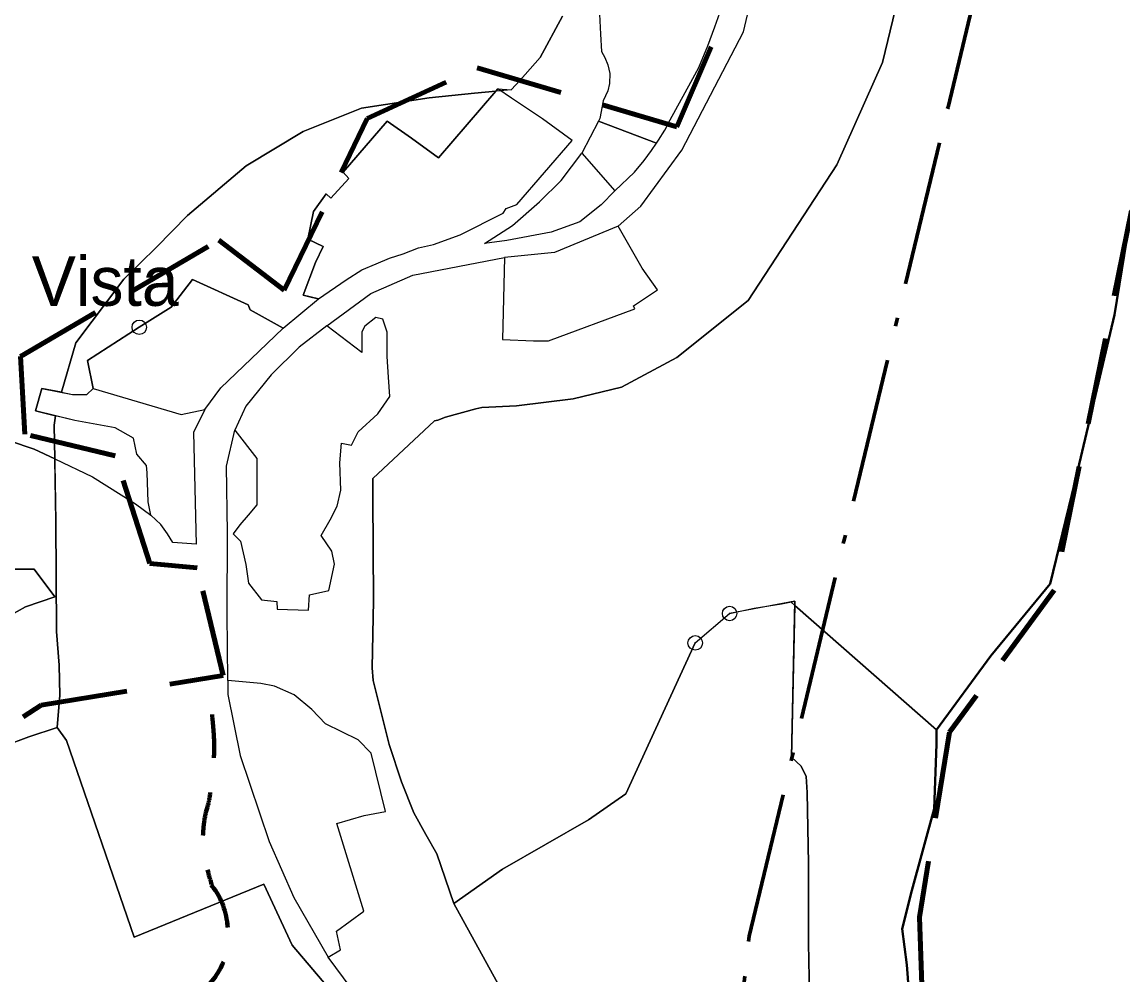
# Model space of a CAD drawing. Extents: x 645880 to 658994, y 884400 to 894744.
# Drawn here: x 657629.6 to 658008.9, y 892199.5 to 892527.8 of the extents above; entities that cross this region are included whole.
import ezdxf
from ezdxf.enums import TextEntityAlignment as Align

# ---------------------------------------------------------------- set-up
doc = ezdxf.new("R2010")
doc.units = 0
doc.header["$LTSCALE"] = 10
doc.header["$PDMODE"] = 32
doc.header["$PDSIZE"] = 5
for name, pattern in [('DOT_DASHED', [7.7, 5, -1.2, 0.3, -1.2]), ('MEDIUM_DASHED', [4.5, 3, -1.5]), ('SHORT_DASHED', [2.7, 1.5, -1.2])]:
    doc.linetypes.add(name, pattern=pattern)
for name, color, linetype, lineweight in [('1', 7, 'Continuous', 25), ('15', 7, 'MEDIUM_DASHED', 100), ('16', 7, 'Continuous', 25), ('17', 7, 'Continuous', 25), ('18', 7, 'Continuous', 25), ('26', 7, 'Continuous', 25), ('41', 7, 'Continuous', 40), ('43', 7, 'Continuous', 25), ('45', 7, 'Continuous', 25), ('54', 7, 'Continuous', 25), ('55', 7, 'Continuous', 25), ('59', 7, 'Continuous', 40), ('8', 7, 'Continuous', 25), ('9', 7, 'Continuous', 25)]:
    doc.layers.add(name, color=color, linetype=linetype, lineweight=lineweight)
doc.layers.add('60', color=7, linetype='Continuous')

msp = doc.modelspace()

# ---------------------------------------------------------------- linework, layer by layer
at = {"layer": '1'}
for points in [[(657833.89, 892469.55), (657829.08, 892464.74), (657821.75, 892458.94), (657811.88, 892455.38), (657796.62, 892452.52), (657788.89, 892451.51), (657798.55, 892457.62), (657807.91, 892465.76), (657815.34, 892473.19), (657822.46, 892482.55)], [(657719.57, 892422.26), (657708.26, 892428.56), (657707.51, 892430.3), (657688.4, 892439), (657680.95, 892429.56), (657670.02, 892422.6), (657652.15, 892411.17), (657654.13, 892401.49), (657684.42, 892392.54), (657692.62, 892394.28), (657698.08, 892401.73), (657708.51, 892411.67)]]:
    msp.add_lwpolyline(points, close=True, dxfattribs=at)
at = {"layer": '15'}
for points in [[(658336.29, 893306.44), (658326.56, 893216.03), (658269.02, 893100.07), (658258.05, 893017.47), (658246.92, 892936.53), (658240.25, 892915.99), (658214.74, 892887.33), (658197.25, 892862.68), (658171.38, 892793.94), (658146.27, 892665.82), (658107.77, 892604.19), (658053.07, 892513.78), (658011.87, 892462.81), (657985.13, 892331.98), (657949.09, 892283.08), (657938.8, 892219.4), (657941.76, 892133.42), (658005.57, 891968.55), (658020.45, 891905.51)], [(657659.98, 891872.19), (657653.31, 891953.19), (657553.31, 891930.32), (657555.21, 891971.29), (657519.02, 892066.59), (657500.92, 892060.88), (657427.26, 892200.13), (657465.85, 892203.1), (657554.9, 892238.74), (657636.17, 892292.45), (657698.87, 892302.6), (657689.96, 892339.72), (657673.64, 892341.21), (657661.76, 892378.34), (657630.59, 892385.76), (657629.11, 892412.49), (657697.38, 892452.59), (657719.98, 892435.41), (657748.55, 892494.5), (657786.44, 892511.99), (657855.22, 892491.64), (657891.81, 892577.33)]]:
    msp.add_lwpolyline(points, dxfattribs=at)
at = {"layer": '16'}
for points in [[(657641.76, 892284.78), (657642.7, 892295.91), (657642.46, 892306.25), (657641.51, 892317.74), (657641.27, 892355.86), (657640.89, 892377.28), (657633.78, 892380.66), (657617.03, 892386.27), (657609.56, 892389.45), (657609.56, 892393.74), (657606.1, 892404.12), (657603.75, 892406.61), (657599.96, 892406.62)], [(657554.13, 892311.79), (657554.13, 892319.84), (657559.4, 892328.64), (657562.22, 892334.26), (657575.23, 892338.19), (657580.1, 892337.81), (657587.04, 892336.67), (657595.08, 892334.91), (657599.56, 892335.75), (657608.31, 892339.25), (657633.81, 892339.25), (657640.93, 892329.75), (657630.81, 892326.25), (657625.11, 892323.1), (657622.12, 892319.05), (657625.15, 892310.12), (657620.91, 892296.57), (657619.41, 892287.86), (657618.04, 892276.14)], [(657618.04, 892276.14), (657623.33, 892278.32), (657631.97, 892281.51), (657641.76, 892284.78)]]:
    msp.add_lwpolyline(points, dxfattribs=at)
at = {"layer": '17'}
for points in [[(657808.16, 892515.52), (657815.77, 892529.8)], [(657792.8, 892503.89), (657793.56, 892504.78), (657798.09, 892504.4), (657801.28, 892507.68), (657808.16, 892515.52)], [(657792.8, 892503.89), (657785.44, 892503.19), (657769.9, 892501.66), (657746.6, 892498.05), (657726.5, 892490.09), (657706.79, 892478.26), (657686.65, 892461.16), (657675.99, 892450.23), (657664.66, 892439.19), (657648.18, 892417.2), (657643.22, 892400.19)], [(657643.22, 892400.19), (657648.18, 892417.2), (657664.66, 892439.19), (657675.99, 892450.23), (657686.65, 892461.16), (657706.79, 892478.26), (657726.5, 892490.09), (657746.6, 892498.05), (657769.9, 892501.66), (657785.44, 892503.19), (657792.8, 892503.89)], [(657735.95, 892467.06), (657742.22, 892473.87), (657740.21, 892476.05), (657755.46, 892493.61), (657763.79, 892487.72), (657773.08, 892480.92), (657792.8, 892503.89)], [(657728.13, 892452.94), (657730, 892462.44), (657734.45, 892468.56), (657735.95, 892467.06)], [(657731.75, 892432.44), (657729.25, 892432.94), (657726.48, 892433.68), (657730.75, 892444.94), (657733.37, 892450.44), (657728.13, 892452.94)], [(657670.02, 892422.6), (657680.95, 892429.56), (657688.4, 892439)], [(657688.4, 892439), (657707.51, 892430.3), (657708.26, 892428.56), (657719.57, 892422.26), (657731.75, 892432.44)], [(657643.22, 892400.19), (657647, 892399.44), (657652, 892399.44), (657654.13, 892401.49), (657652.15, 892411.17), (657670.02, 892422.6)], [(657391.42, 892400.35), (657599.96, 892406.62), (657603.75, 892406.61), (657606.1, 892404.12), (657609.56, 892393.74), (657609.56, 892389.45), (657617.03, 892386.27), (657633.78, 892380.66), (657640.89, 892377.28)], [(657641.21, 892392.12), (657634.32, 892393.87), (657636.46, 892401.53), (657643.22, 892400.19)], [(657641.21, 892392.12), (657640.69, 892388.83), (657640.89, 892377.28), (657653.91, 892371.08)], [(657640.89, 892377.28), (657640.69, 892388.83), (657641.21, 892392.12)], [(657674, 892357.85), (657673.13, 892362.44), (657672.75, 892372.44), (657672.5, 892374.94), (657669.13, 892378.94), (657668, 892384.44), (657661.75, 892387.94), (657647.87, 892390.44), (657641.21, 892392.12)], [(657653.91, 892371.08), (657668.77, 892361.83), (657674, 892357.85)]]:
    msp.add_lwpolyline(points, dxfattribs=at)
msp.add_lwpolyline([(657726.48, 892433.68), (657729.25, 892432.94), (657731.75, 892432.44)], close=True, dxfattribs=at)
msp.add_point((657670.02, 892422.6), dxfattribs=at)
at = {"layer": '18'}
msp.add_lwpolyline([(657618.04, 892276.14), (657619.41, 892287.86), (657620.91, 892296.57), (657625.15, 892310.12), (657622.12, 892319.05), (657625.11, 892323.1), (657630.81, 892326.25), (657640.93, 892329.75), (657633.81, 892339.25), (657608.31, 892339.25), (657599.56, 892335.75), (657595.08, 892334.91), (657587.04, 892336.67), (657580.1, 892337.81), (657575.23, 892338.19)], dxfattribs=at)
at = {"layer": '26'}
for points in [[(657900.53, 892237.87), (657900.15, 892262.37), (657899.78, 892267.87), (657898.03, 892271.37), (657894.65, 892274.55), (657895.9, 892328.23), (657873.37, 892324)], [(657861.53, 892313.87), (657837.65, 892261.87), (657824.78, 892252.87), (657795.12, 892235.95), (657778.36, 892224.09)], [(657969.06, 891989.78), (657961.73, 892004.82), (657954.74, 892019.84), (657949.21, 892033.48), (657942.92, 892051.1), (657938.43, 892067.67), (657937.13, 892073.16), (657935.47, 892080.23), (657923.74, 892112.25), (657917.89, 892123.87), (657914.25, 892132.34), (657909.36, 892148.03), (657906.8, 892160.8), (657903.04, 892176.6), (657900.88, 892192.55), (657900.54, 892210.44), (657900.5, 892229.56), (657900.53, 892237.87)], [(657778.36, 892224.09), (657800.5, 892183.77), (657806.51, 892172.24), (657812.46, 892161.09), (657816.57, 892152.85), (657808.89, 892139.52)]]:
    msp.add_lwpolyline(points, dxfattribs=at)
for p in [(657873.37, 892324), (657861.53, 892313.87)]:
    msp.add_point(p, dxfattribs=at)
at = {"layer": '41', "linetype": 'SHORT_DASHED', "lineweight": 80}
for centre, radius, start, end in [((657675.2, 892214.63), 25.26, 5.1262, 39.8988), ((657676.52, 892212.91), 24.19, 302.9189, 10.4492)]:
    msp.add_arc(centre, radius, start, end, dxfattribs=at)
msp.add_open_spline([(657695.09, 892289.21), (657695.09, 892289.19), (657695.56, 892284.19), (657696.14, 892276.15), (657694.44, 892263.9), (657694.39, 892259.85), (657692.57, 892254.9), (657691.79, 892247.35), (657692.05, 892240.58), (657693.09, 892237.2), (657694.13, 892233.55), (657694.91, 892230.69)], degree=3, dxfattribs=at)
at = {"layer": '43'}
for points in [[(657835, 892457.44), (657842.84, 892464.35), (657856.87, 892483.62), (657878.16, 892524.36), (657882.72, 892543.97), (657883.73, 892554.62), (657888.13, 892574.56), (657896.4, 892594.5), (657916, 892624.42), (657931.14, 892647.6)], [(657983.67, 892634.59), (657951.45, 892588.47), (657944.08, 892577.4), (657941.75, 892570.16), (657934.47, 892548.33), (657930.56, 892532.28), (657926.03, 892513.82), (657910.35, 892478.61), (657879.77, 892431.81), (657855.18, 892412.21), (657836.09, 892401.96), (657819.49, 892397.93), (657800.02, 892395.5), (657787.99, 892394.92), (657785.98, 892394.47), (657775.48, 892391.59), (657772.88, 892390.58), (657771.72, 892390.37)], [(657983.67, 892634.59), (657951.45, 892588.47), (657944.08, 892577.4), (657941.75, 892570.16), (657934.47, 892548.33), (657930.56, 892532.28), (657926.03, 892513.82), (657910.35, 892478.61), (657879.77, 892431.81), (657855.18, 892412.21), (657836.09, 892401.96), (657819.49, 892397.93), (657800.02, 892395.5), (657787.99, 892394.92), (657785.98, 892394.47), (657775.48, 892391.59), (657772.88, 892390.58), (657771.72, 892390.37)], [(657848.89, 892487.05), (657851.02, 892490.55), (657852.89, 892494.05), (657860.02, 892507.05), (657862.77, 892512.05), (657865.89, 892519.55), (657868.27, 892526.05), (657870.64, 892532.55), (657872.89, 892540.55), (657874.52, 892548.55), (657876.52, 892557.55), (657877.77, 892564.05), (657879.27, 892570.55), (657881.39, 892579.55), (657883.89, 892587.05), (657862.89, 892598.55), (657859.77, 892599.55), (657861.77, 892603.55), (657872.77, 892621.55), (657893.02, 892612.05), (657902.02, 892634.05)], [(657825.9, 892557.56), (657826.27, 892554.55), (657826.64, 892549.05), (657827.14, 892545.05), (657827.77, 892539.55), (657828.27, 892535.05), (657828.89, 892523.55), (657829.27, 892517.55), (657830.39, 892515.55), (657831.39, 892513.05), (657832.14, 892510.05), (657832.02, 892506.55), (657831.39, 892504.05), (657829.77, 892500.55), (657828.64, 892494.55), (657828.24, 892493.56), (657848.19, 892486.01), (657848.89, 892487.05)], [(657895.87, 892326.7), (657944.68, 892283.89), (657963.4, 892309.47), (657983.82, 892334.23), (657992.29, 892369.17), (658005.91, 892426.94), (658011.87, 892462.81), (658033.19, 892488.35), (658043.68, 892500.77)], [(657795.78, 892446.68), (657795.13, 892418.44), (657805.87, 892417.94), (657811, 892417.94), (657840.75, 892428.94), (657840.25, 892429.94), (657848.5, 892435.44), (657843.25, 892442.94), (657835, 892457.44)], [(657734.65, 892423.04), (657749.77, 892434.26), (657764.3, 892440.52), (657795.78, 892446.68)], [(657702.91, 892387.1), (657710.5, 892377.44), (657710.56, 892361.47), (657707.49, 892357.83), (657704.65, 892354.57), (657702.41, 892351.42), (657704.87, 892348.94), (657706.68, 892340.85), (657707.7, 892334.44), (657712.17, 892328.75), (657717.45, 892328.14), (657717.5, 892325.44), (657728.32, 892325.09), (657728.63, 892330.48), (657735.37, 892331.94), (657737.25, 892340.94), (657736.35, 892345.42), (657732.69, 892350.91), (657735.74, 892356.3), (657738.18, 892360.98), (657739.5, 892366.47), (657739.1, 892375.9), (657739.64, 892382.64), (657743.15, 892381.96), (657745.45, 892386.56), (657752.19, 892392.81), (657756.35, 892398.72), (657755.89, 892405.37), (657755.44, 892412.5), (657755.44, 892420.88), (657753.87, 892425.44), (657751.5, 892425.94), (657747.75, 892422.94), (657746.67, 892421.01), (657746.63, 892413.94), (657734.65, 892423.04)], [(657771.72, 892390.37), (657750.53, 892370.54), (657750.42, 892364.06), (657750.65, 892328.46), (657750.22, 892305.26), (657750.59, 892300.97), (657756.1, 892278.92), (657760.35, 892265.98)], [(657771.72, 892390.37), (657750.53, 892370.54), (657750.42, 892364.06), (657750.65, 892328.46), (657750.22, 892305.26), (657750.59, 892300.97), (657756.1, 892278.92), (657760.35, 892265.98)], [(657700.56, 892300.88), (657700.26, 892323.87), (657700.38, 892351.83), (657700.09, 892374.76), (657702.91, 892387.1)], [(657873.37, 892324), (657881.78, 892325.87), (657891.2, 892327.35), (657895.9, 892328.23), (657895.87, 892326.7)], [(657891.2, 892327.35), (657895.9, 892328.23), (657895.87, 892326.7)], [(657895.87, 892326.7), (657894.53, 892327.87), (657891.2, 892327.35)], [(657778.36, 892224.09), (657795.12, 892235.95), (657824.78, 892252.87), (657837.65, 892261.87), (657861.53, 892313.87), (657873.37, 892324)], [(657735.04, 892205.6), (657739.29, 892208.08), (657737.96, 892214.62), (657747.43, 892221.45), (657738.08, 892251.71), (657747.5, 892254.44), (657754.78, 892255.81), (657749.87, 892275.94), (657745.37, 892280.44), (657734.13, 892285.94), (657729.5, 892290.94), (657723.37, 892295.94), (657716.63, 892298.94), (657711.87, 892299.94), (657700.56, 892300.88)], [(657760.35, 892265.98), (657764.58, 892255.38), (657768.75, 892247.87), (657772.51, 892241.19), (657778.36, 892224.09)], [(657760.35, 892265.98), (657764.58, 892255.38), (657768.75, 892247.87), (657772.51, 892241.19), (657778.36, 892224.09)], [(657778.36, 892224.09), (657800.5, 892183.77), (657806.51, 892172.24), (657812.46, 892161.09), (657816.57, 892152.85), (657808.89, 892139.52), (657794.99, 892142.08), (657789.56, 892139.52), (657786.42, 892137.64), (657779.19, 892136.74), (657769.74, 892137.93), (657758.69, 892137.73), (657762.43, 892154.84), (657761.75, 892166.17), (657751.28, 892183.75), (657735.04, 892205.6)]]:
    msp.add_lwpolyline(points, dxfattribs=at)
at = {"layer": '45', "linetype": 'DOT_DASHED', "lineweight": 70}
msp.add_lwpolyline([(658032.74, 891178.84), (657962.16, 891450), (657912.65, 891632.07), (657880.45, 891775.54), (657862.08, 891924.55), (657862.75, 892057.96), (657880.13, 892212.9), (657948.63, 892498.48), (658035.94, 892864.43), (658113.04, 893179.94), (658123.49, 893235.71), (658127.65, 893288.31), (658121.92, 893384.59), (658110.78, 893490.65), (658118.71, 893627.43), (658149.69, 893744.87)], dxfattribs=at)
at = {"layer": '54'}
for points in [[(658039.48, 891829.06), (658048.04, 891814.67), (658055.03, 891820.85), (658033.16, 891856.93), (658014.45, 891880.86), (658017.85, 891897.37), (658017.85, 891907.27), (657997.43, 891981.01), (657982.12, 892018.15), (657960.85, 892076.74), (657948.09, 892113.06), (657941.28, 892132.04), (657937.88, 892157.62), (657934.48, 892203.01), (657932.77, 892215.39), (657936.18, 892228.6), (657943.83, 892256.66), (657944.68, 892278.94), (657944.68, 892283.89), (657895.87, 892326.7), (657894.65, 892274.55)], [(657894.65, 892274.55), (657898.03, 892271.37), (657899.78, 892267.87), (657900.15, 892262.37), (657900.53, 892237.87), (657900.5, 892229.56)], [(657900.5, 892229.56), (657900.54, 892210.44), (657900.88, 892192.55)]]:
    msp.add_lwpolyline(points, dxfattribs=at)
at = {"layer": '55'}
for points in [[(657771.72, 892390.37), (657772.88, 892390.58), (657775.48, 892391.59), (657785.98, 892394.47), (657787.99, 892394.92), (657800.02, 892395.5), (657819.49, 892397.93), (657836.09, 892401.96), (657855.18, 892412.21), (657879.77, 892431.81), (657910.35, 892478.61), (657926.03, 892513.82), (657930.56, 892532.28), (657934.47, 892548.33), (657941.75, 892570.16), (657944.08, 892577.4), (657951.45, 892588.47), (657983.68, 892634.59)], [(657815.77, 892529.8), (657808.16, 892515.52), (657801.28, 892507.68), (657798.09, 892504.4), (657785.44, 892503.19), (657769.9, 892501.66), (657746.6, 892498.05), (657726.5, 892490.09), (657706.79, 892478.26), (657686.65, 892461.16), (657675.99, 892450.23), (657664.66, 892439.19), (657648.18, 892417.2), (657643.22, 892400.19), (657636.46, 892401.53), (657634.32, 892393.87), (657641.21, 892392.12), (657640.69, 892388.83), (657641.27, 892355.86), (657641.51, 892317.74), (657642.46, 892306.25), (657642.7, 892295.91), (657641.76, 892284.78), (657644.99, 892280.24)], [(657816.57, 892152.85), (657800.5, 892183.77), (657778.36, 892224.09), (657772.51, 892241.19), (657768.75, 892247.87), (657764.58, 892255.38), (657760.35, 892265.98), (657756.1, 892278.92), (657750.59, 892300.97), (657750.22, 892305.26), (657750.65, 892328.46), (657750.42, 892364.06), (657750.53, 892370.54), (657771.72, 892390.37)], [(657644.99, 892280.24), (657668.25, 892212.45), (657712.92, 892230.71), (657722.71, 892209.8), (657736.9, 892193.02), (657722.75, 892186.87), (657715.33, 892177.95), (657691.39, 892169.48), (657668.37, 892162.48), (657663.8, 892153.01), (657655.99, 892149.6), (657644.66, 892141.63), (657634.11, 892138.44), (657639.17, 892130.9), (657652.93, 892108.49), (657655.19, 892117.63), (657657.26, 892122.02), (657660.73, 892125.31), (657665.2, 892127.22), (657669.2, 892126.84), (657685.96, 892114.9), (657684.13, 892095.89), (657685.62, 892018.98)]]:
    msp.add_lwpolyline(points, dxfattribs=at)
at = {"layer": '59'}
for points in [[(658074.53, 892542.9), (658051.68, 892510.24), (658033.19, 892488.35), (658011.87, 892462.81), (658005.91, 892426.94), (657992.29, 892369.17), (657983.82, 892334.23), (657963.4, 892309.47), (657944.68, 892283.89), (657944.68, 892278.94)], [(657944.68, 892278.94), (657943.83, 892256.66), (657936.18, 892228.6), (657932.77, 892215.39), (657934.48, 892203.01), (657937.88, 892157.62), (657941.28, 892132.04), (657948.09, 892113.06), (657960.85, 892076.74), (657982.12, 892018.15), (657997.43, 891981.01), (658017.85, 891907.27)]]:
    msp.add_lwpolyline(points, dxfattribs=at)
at = {"layer": '8'}
for points in [[(657819.13, 892486.94), (657808.97, 892494.42), (657798.28, 892501.56), (657793.56, 892504.78), (657773.08, 892480.92), (657763.79, 892487.72), (657755.46, 892493.61), (657740.21, 892476.05), (657742.22, 892473.87), (657735.95, 892467.06), (657734.45, 892468.56), (657730, 892462.44), (657728.13, 892452.94), (657733.37, 892450.44), (657730.75, 892444.94), (657726.48, 892433.68), (657729.25, 892432.94), (657731.75, 892432.44), (657741.25, 892438.94), (657746.63, 892442.44), (657751.63, 892444.44), (657756.25, 892446.44), (657760.87, 892447.94), (657766.25, 892449.94), (657771.38, 892451.17), (657780.57, 892454.49), (657795.37, 892461.94), (657796.43, 892463.56), (657800.13, 892464.94)], [(657835, 892457.44), (657813.09, 892448.35), (657795.78, 892446.68), (657795.13, 892418.44), (657805.87, 892417.94), (657811, 892417.94), (657840.75, 892428.94), (657840.25, 892429.94), (657848.5, 892435.44), (657843.25, 892442.94)], [(657734.65, 892423.04), (657725.06, 892415.72), (657715.43, 892406.25), (657706.75, 892395.44), (657702.91, 892387.1), (657710.5, 892377.44), (657710.56, 892361.47), (657707.49, 892357.83), (657704.65, 892354.57), (657702.41, 892351.42), (657704.87, 892348.94), (657706.68, 892340.85), (657707.7, 892334.44), (657712.17, 892328.75), (657717.45, 892328.14), (657717.5, 892325.44), (657728.32, 892325.09), (657728.63, 892330.48), (657735.37, 892331.94), (657737.25, 892340.94), (657736.35, 892345.42), (657732.69, 892350.91), (657735.74, 892356.3), (657738.18, 892360.98), (657739.5, 892366.47), (657739.1, 892375.9), (657739.64, 892382.64), (657743.15, 892381.96), (657745.45, 892386.56), (657752.19, 892392.81), (657756.35, 892398.72), (657755.89, 892405.37), (657755.44, 892412.5), (657755.44, 892420.88), (657753.87, 892425.44), (657751.5, 892425.94), (657747.75, 892422.94), (657746.67, 892421.01), (657746.63, 892413.94)], [(657636.46, 892401.53), (657647, 892399.44), (657652, 892399.44), (657654.13, 892401.49), (657684.42, 892392.54), (657692.62, 892394.28), (657688.67, 892386.3), (657689.61, 892347.91), (657681.63, 892348.44), (657679.75, 892351.4), (657677.4, 892354.62), (657674, 892357.85), (657673.13, 892362.44), (657672.75, 892372.44), (657672.5, 892374.94), (657669.13, 892378.94), (657668, 892384.44), (657661.75, 892387.94), (657647.87, 892390.44), (657634.32, 892393.87)], [(657700.56, 892300.88), (657700.57, 892296.04), (657704.79, 892275.08), (657714.76, 892245.49), (657723.21, 892226.22), (657735.04, 892205.6), (657739.29, 892208.08), (657737.96, 892214.62), (657747.43, 892221.45), (657738.08, 892251.71), (657747.5, 892254.44), (657754.78, 892255.81), (657749.87, 892275.94), (657745.37, 892280.44), (657734.13, 892285.94), (657729.5, 892290.94), (657723.37, 892295.94), (657716.63, 892298.94), (657711.87, 892299.94)]]:
    msp.add_lwpolyline(points, close=True, dxfattribs=at)
for points in [[(657840.64, 892476.05), (657843.89, 892480.05), (657846.52, 892483.55), (657848.19, 892486.01), (657828.24, 892493.56), (657822.46, 892482.55)], [(657822.46, 892482.55), (657833.89, 892469.55), (657840.64, 892476.05)]]:
    msp.add_lwpolyline(points, dxfattribs=at)
at = {"layer": '9'}
msp.add_lwpolyline([(657634.11, 892138.44), (657644.66, 892141.63), (657655.99, 892149.6), (657663.8, 892153.01), (657668.37, 892162.48), (657692.08, 892169.69), (657715.33, 892177.95), (657722.75, 892186.87), (657736.9, 892193.02), (657722.71, 892209.8), (657712.92, 892230.71), (657668.25, 892212.45), (657644.99, 892280.24), (657641.76, 892284.78), (657631.97, 892281.51), (657623.33, 892278.32)], dxfattribs=at)

# ---------------------------------------------------------------- texts
at = {"layer": '60'}
msp.add_text('Bella Vista', height=17, dxfattribs=at).set_placement((657629.84, 892429.98), align=Align.CENTER)

doc.saveas('drawing.dxf')
